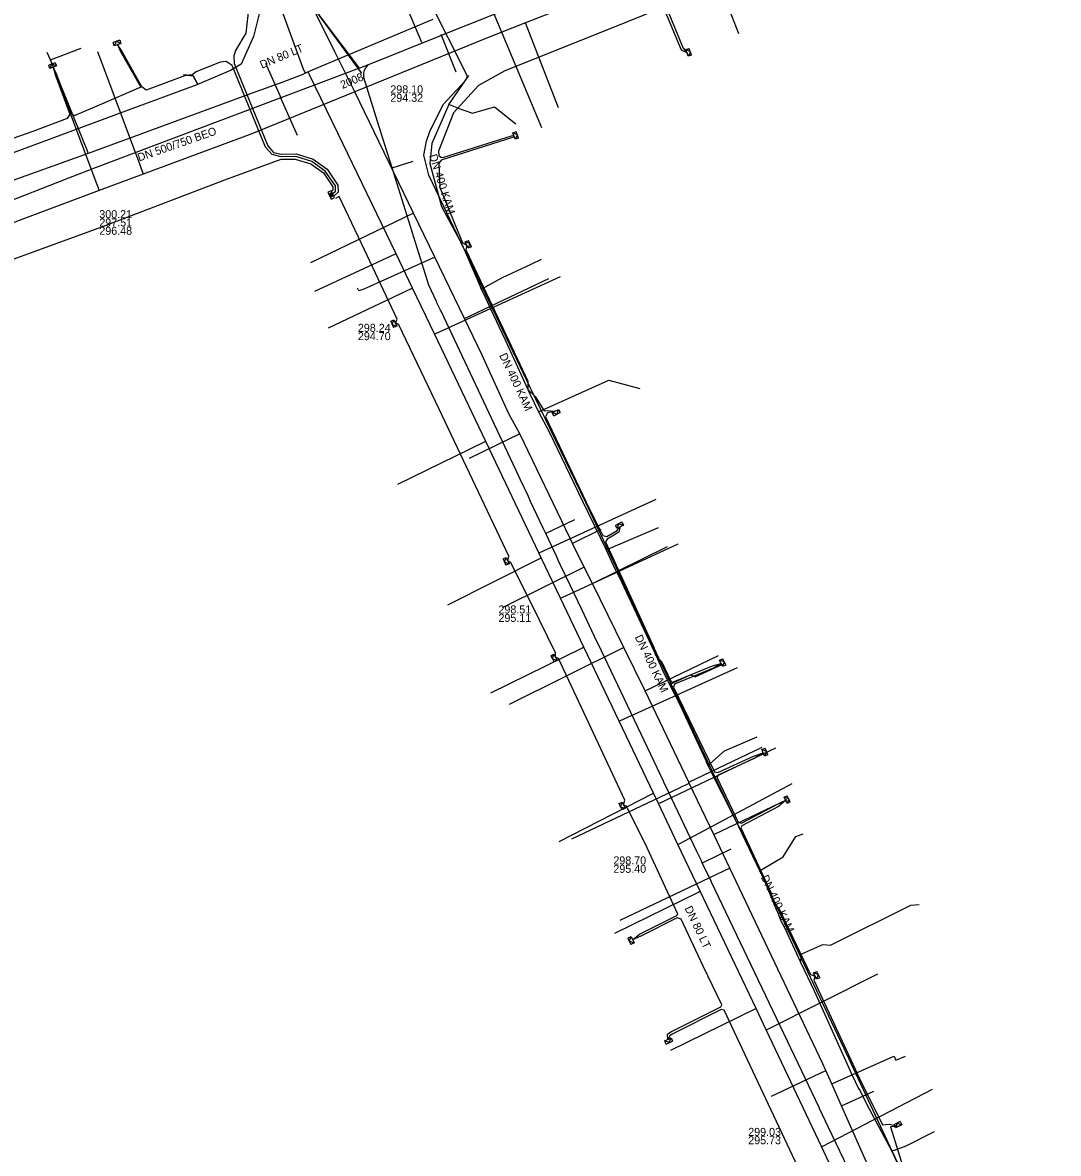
# Model space of a CAD drawing. Extents: x -600391 to -599491, y -1160176 to -1159402.
# Drawn here: x -600264.6 to -600161.2, y -1159777.8 to -1159664.8 of the extents above; entities that cross this region are included whole.
import ezdxf

# ---------------------------------------------------------------- set-up
doc = ezdxf.new("R2010")
doc.units = 0
for name, color, linetype in [('28', 7, 'Continuous'), ('31', 7, 'Continuous'), ('UPC_ok_linie', 7, 'Continuous'), ('Vrstva 1', 7, 'Continuous'), ('Vrstva 12', 7, 'Continuous'), ('Vrstva 13', 7, 'Continuous'), ('Vrstva 15', 7, 'Continuous'), ('Vrstva 16', 7, 'Continuous'), ('Vrstva 42', 7, 'Continuous'), ('Vrstva 43', 7, 'Continuous'), ('Vrstva 55', 7, 'Continuous'), ('Vrstva 9', 7, 'Continuous')]:
    doc.layers.add(name, color=color, linetype=linetype)

# ---------------------------------------------------------------- blocks, each defined once
blk = doc.blocks.new('NN630')
at = {"layer": '31'}
for points in [[(0, -0.7), (-0.7, 0)], [(-0.7, -0.7), (-0.7, 0), (0.7, 0), (0.7, -0.7)], [(-0.7, -0.7), (0.7, -0.7)], [(0, -0.7), (0.7, 0)]]:
    blk.add_lwpolyline(points, dxfattribs=at)
blk = doc.blocks.new('NN620')
at = {"layer": '28'}
for points in [[(0.75, 0), (-0.75, 0)], [(-0.75, 0), (-0.75, -0.75)], [(0.75, -0.75), (0.75, 0)], [(-0.75, -0.75), (0.75, -0.75)], [(0.37, -0.18), (-0.38, -0.18)], [(-0.38, -0.18), (-0.38, -0.56)], [(-0.38, -0.56), (0.37, -0.56)], [(0.32, -0.23), (-0.33, -0.23)], [(-0.33, -0.23), (-0.33, -0.51)], [(-0.33, -0.51), (0.32, -0.51)], [(0.27, -0.27), (-0.28, -0.27)], [(-0.28, -0.27), (-0.28, -0.46)], [(-0.28, -0.46), (0.27, -0.46)], [(0.23, -0.32), (-0.23, -0.32)], [(-0.23, -0.32), (-0.23, -0.42)], [(-0.23, -0.42), (0.23, -0.42)], [(-0.19, -0.37), (0.19, -0.37)], [(0.23, -0.42), (0.23, -0.32)], [(0.27, -0.46), (0.27, -0.27)], [(0.32, -0.51), (0.32, -0.23)], [(0.37, -0.56), (0.37, -0.18)]]:
    blk.add_lwpolyline(points, dxfattribs=at)

msp = doc.modelspace()

# ---------------------------------------------------------------- linework, layer by layer
at = {"layer": 'UPC_ok_linie'}
for p, q in [((-600222.07, -1159672.98), (-600220.06, -1159670.1)), ((-600221.23, -1159673.3), (-600222.07, -1159672.98)), ((-600206.36, -1159717.5), (-600201.11, -1159715.26))]:
    msp.add_line(p, q, dxfattribs=at)
for points in [[(-600222.07, -1159672.98), (-600223.78, -1159676.87), (-600223.98, -1159678.89), (-600222.8, -1159683.16), (-600220.73, -1159687.01), (-600219.02, -1159690.99), (-600218.84, -1159691.43)], [(-600221.23, -1159673.3), (-600219.69, -1159673.85), (-600217.51, -1159673.22), (-600215.38, -1159674.93)], [(-600218.84, -1159691.43), (-600216.7, -1159690.26), (-600213.83, -1159688.93), (-600212.8, -1159688.45)], [(-600218.84, -1159691.43), (-600218.58, -1159691.95), (-600217.89, -1159693.4), (-600216.44, -1159696.5), (-600213.99, -1159701.89), (-600213.1, -1159703.68)], [(-600213.1, -1159703.68), (-600206.08, -1159700.53), (-600202.98, -1159701.37)], [(-600213.1, -1159703.68), (-600212.07, -1159705.64), (-600208.71, -1159712.61), (-600206.36, -1159717.5)], [(-600206.36, -1159717.5), (-600205.52, -1159719.32), (-600205.05, -1159720.19), (-600204.83, -1159720.68), (-600201.34, -1159728.08), (-600200.7, -1159729.59), (-600200.26, -1159730.47), (-600200.04, -1159730.95)], [(-600200.04, -1159730.95), (-600197.93, -1159729.97), (-600197.45, -1159730.17), (-600194.7, -1159728.91)], [(-600200.04, -1159730.95), (-600199.09, -1159732.73), (-600196.38, -1159738.52), (-600196.33, -1159738.72), (-600196.16, -1159739.1)], [(-600196.16, -1159739.1), (-600195.98, -1159738.87), (-600194.54, -1159737.57), (-600191.26, -1159736.17)], [(-600196.16, -1159739.1), (-600195.97, -1159739.51), (-600194.76, -1159741.88), (-600192.01, -1159747.32), (-600190.97, -1159749.54)], [(-600190.97, -1159749.54), (-600188.68, -1159748.16), (-600187.4, -1159746.13), (-600186.66, -1159745.88)], [(-600190.97, -1159749.54), (-600189.42, -1159753.25), (-600189.21, -1159753.77), (-600188.9, -1159754.57)], [(-600186.93, -1159758.68), (-600186.89, -1159758.44), (-600186.8, -1159757.87), (-600184.72, -1159756.94), (-600183.95, -1159757), (-600175.93, -1159752.98), (-600175.08, -1159752.94)], [(-600188.9, -1159754.57), (-600188.54, -1159755.21), (-600186.93, -1159758.68)], [(-600186.93, -1159758.68), (-600185.59, -1159761.56), (-600181.82, -1159769.9), (-600181.14, -1159771.3), (-600180.99, -1159771.54), (-600180.31, -1159772.92), (-600177.86, -1159777.5)], [(-600177.86, -1159777.5), (-600177.54, -1159777.46), (-600176.4, -1159777.03), (-600173.57, -1159775.61)], [(-600177.86, -1159777.5), (-600170.81, -1159792.72), (-600170.15, -1159793.98), (-600169.79, -1159794.82)]]:
    msp.add_lwpolyline(points, dxfattribs=at)
at = {"layer": 'Vrstva 1'}
for points in [[(-600230.8, -1159669.87), (-600230.8, -1159669.82), (-600244.13, -1159651.58)], [(-600224.77, -1159666.77), (-600226.13, -1159663.54)], [(-600221.33, -1159669.76), (-600222.82, -1159665.98)], [(-600238.79, -1159672.43), (-600240.35, -1159668.87)], [(-600237.2, -1159676.09), (-600238.82, -1159672.43)], [(-600227.74, -1159679.3), (-600225.62, -1159678.64)], [(-600209.5, -1159714.48), (-600212.39, -1159715.86)], [(-600193.9, -1159747.41), (-600196.71, -1159748.76)]]:
    msp.add_lwpolyline(points, dxfattribs=at)
at = {"layer": 'Vrstva 13'}
for p, q in [((-600197.8, -1159653.93), (-600193.12, -1159665.9)), ((-600218.25, -1159662.29), (-600212.82, -1159675.29)), ((-600261.87, -1159668.51), (-600258.8, -1159667.34)), ((-600236.4, -1159669.86), (-600236.64, -1159669.98)), ((-600236.4, -1159669.86), (-600236.55, -1159669.55)), ((-600235.99, -1159670.03), (-600236.13, -1159669.73)), ((-600238.64, -1159670.74), (-600238.65, -1159670.72)), ((-600233.15, -1159675.83), (-600233.13, -1159675.82))]:
    msp.add_line(p, q, dxfattribs=at)
for points in [[(-600236.55, -1159669.55), (-600238.62, -1159663.92), (-600239.77, -1159661.76), (-600245.4, -1159651.67), (-600249.45, -1159643.65), (-600250.94, -1159640.72), (-600257.51, -1159628.87), (-600262.81, -1159619.3), (-600263.06, -1159618.85), (-600264.09, -1159617), (-600272.21, -1159603.6), (-600272.38, -1159603.32)], [(-600223.67, -1159664.49), (-600224.22, -1159664.72), (-600236.13, -1159669.73), (-600236.4, -1159669.86)], [(-600258.09, -1159677.89), (-600258.14, -1159677.72), (-600261.87, -1159668.51), (-600262.18, -1159667.79)], [(-600236.64, -1159669.98), (-600238.64, -1159670.74), (-600241.34, -1159671.7)], [(-600161.18, -1159826.62), (-600168.95, -1159810.66), (-600176.39, -1159794.77), (-600178.7, -1159789.98), (-600183.86, -1159779.17), (-600184.83, -1159777.12), (-600190.37, -1159765.45), (-600191.37, -1159763.33), (-600196.96, -1159751.61), (-600199.19, -1159746.92), (-600201.13, -1159742.84), (-600201.62, -1159741.81), (-600205.05, -1159734.61), (-600208.57, -1159727.22), (-600210.91, -1159722.31), (-600212.83, -1159718.29), (-600213.07, -1159717.78), (-600218.37, -1159706.66), (-600223.5, -1159695.91), (-600225.68, -1159691.33), (-600227.32, -1159687.89), (-600233.15, -1159675.83), (-600235.99, -1159670.03)], [(-600241.34, -1159671.7), (-600258.09, -1159677.89), (-600279.4, -1159685.51), (-600279.76, -1159685.64), (-600286.88, -1159688.33), (-600307.79, -1159695.54), (-600308.6, -1159695.85), (-600320.75, -1159700.28), (-600329.04, -1159703.28)], [(-600227.32, -1159687.89), (-600227.44, -1159687.95), (-600235.47, -1159691.67)], [(-600223.5, -1159695.91), (-600223.37, -1159695.85), (-600210.92, -1159690.17)], [(-600225.68, -1159691.33), (-600225.77, -1159691.37), (-600234.12, -1159695.34)], [(-600218.37, -1159706.66), (-600218.47, -1159706.7), (-600227.19, -1159710.95)], [(-600213.07, -1159717.78), (-600212.98, -1159717.74), (-600201.35, -1159712.41)], [(-600210.91, -1159722.31), (-600210.73, -1159722.24), (-600199.16, -1159716.89)], [(-600212.83, -1159718.29), (-600212.93, -1159718.34), (-600222.19, -1159723.02)], [(-600208.57, -1159727.22), (-600208.76, -1159727.32), (-600217.89, -1159731.81)], [(-600205.05, -1159734.61), (-600204.93, -1159734.55), (-600193.23, -1159729.25)], [(-600201.13, -1159742.84), (-600201.08, -1159742.82), (-600189.4, -1159737.28)], [(-600199.19, -1159746.92), (-600198.98, -1159746.83), (-600187.76, -1159740.85)], [(-600201.62, -1159741.81), (-600201.72, -1159741.86), (-600211.07, -1159746.68)], [(-600196.96, -1159751.61), (-600197.11, -1159751.68), (-600205.52, -1159755.83)], [(-600190.37, -1159765.45), (-600190.35, -1159765.44), (-600179.2, -1159759.85)], [(-600191.37, -1159763.33), (-600191.42, -1159763.35), (-600199.91, -1159767.52)], [(-600184.83, -1159777.12), (-600184.78, -1159777.1), (-600173.76, -1159771.38)]]:
    msp.add_lwpolyline(points, dxfattribs=at)
at = {"layer": 'Vrstva 16'}
for points in [[(-600256.94, -1159591.71), (-600258.09, -1159592.42), (-600270.56, -1159600.02), (-600267.59, -1159605.02), (-600264.25, -1159610.67), (-600261.26, -1159616.28), (-600261.19, -1159616.42), (-600258.03, -1159622.25), (-600255.77, -1159626.44), (-600244.99, -1159645.87), (-600239.51, -1159655.75), (-600239.15, -1159656.4), (-600233.5, -1159667.64)], [(-600192.98, -1159656.42), (-600214.42, -1159664.83), (-600218.2, -1159666.31), (-600231.45, -1159671.73), (-600241.75, -1159675.9), (-600252.59, -1159679.95), (-600257, -1159681.59), (-600273.19, -1159687.64), (-600281.2, -1159690.52), (-600282.61, -1159691.03), (-600286.19, -1159692.31), (-600306.49, -1159699.61), (-600317.46, -1159703.55), (-600317.98, -1159703.74), (-600319.12, -1159704.16), (-600321.16, -1159704.92), (-600324.82, -1159706.29), (-600332.07, -1159708.92)], [(-600211.1, -1159673.3), (-600214.02, -1159665.86), (-600214.42, -1159664.83)], [(-600257.17, -1159667.69), (-600252.98, -1159678.92), (-600252.59, -1159679.95)], [(-600231.45, -1159671.73), (-600233.5, -1159667.64)], [(-600261.58, -1159669.33), (-600257.52, -1159680.19), (-600257, -1159681.59)], [(-600179.95, -1159779.58), (-600182.83, -1159773.03), (-600183.81, -1159770.84), (-600184.41, -1159769.5), (-600184.7, -1159768.84), (-600187.26, -1159763.46), (-600194, -1159749.3), (-600195.6, -1159745.92), (-600198.05, -1159740.79), (-600198.1, -1159740.69), (-600202.44, -1159731.56), (-600204.57, -1159727.26), (-600207.73, -1159720.86), (-600208.54, -1159719.23), (-600209.72, -1159716.84), (-600209.96, -1159716.35), (-600214.97, -1159705.89), (-600216.09, -1159703.89), (-600218.78, -1159697.96), (-600220.51, -1159694.38), (-600223.46, -1159688.25), (-600225.59, -1159683.84), (-600231.45, -1159671.73)], [(-600225.59, -1159683.84), (-600235.89, -1159688.82)], [(-600223.46, -1159688.25), (-600230.57, -1159691.42)], [(-600220.51, -1159694.38), (-600212.08, -1159690.38)], [(-600230.57, -1159691.42), (-600231.07, -1159691.61), (-600231.2, -1159691.35)], [(-600214.97, -1159705.89), (-600220.03, -1159708.37)], [(-600206.89, -1159715.45), (-600209.72, -1159716.84)], [(-600207.73, -1159720.86), (-600200.23, -1159717.15)], [(-600208.54, -1159719.23), (-600216.68, -1159723.25), (-600216.69, -1159723.26)], [(-600204.57, -1159727.26), (-600216.03, -1159732.94)], [(-600202.44, -1159731.56), (-600195.12, -1159728.06)], [(-600198.1, -1159740.69), (-600190.76, -1159737.19)], [(-600209.77, -1159746.37), (-600199.04, -1159741.26), (-600198.05, -1159740.79)], [(-600195.6, -1159745.92), (-600188.27, -1159742.43)], [(-600194, -1159749.3), (-600205, -1159754.54)], [(-600183.81, -1159770.84), (-600177.67, -1159768.1)], [(-600177.67, -1159768.1), (-600177.59, -1159768.07), (-600177.41, -1159768.47), (-600176.45, -1159768.07)], [(-600189.84, -1159772.08), (-600184.41, -1159769.5)], [(-600182.83, -1159773.03), (-600179.6, -1159771.59)]]:
    msp.add_lwpolyline(points, dxfattribs=at)
at = {"layer": 'Vrstva 42'}
for points in [[(-600242.04, -1159663.18), (-600242.35, -1159665.85), (-600243.38, -1159667.57), (-600243.55, -1159668.16), (-600243.51, -1159668.9), (-600240.15, -1159677.1), (-600239.59, -1159677.77), (-600238.77, -1159677.96), (-600237.33, -1159677.92), (-600235.63, -1159678.46), (-600234.23, -1159679.46), (-600233.15, -1159681.04), (-600233.13, -1159681.74), (-600233.52, -1159682.11)], [(-600200.86, -1159663.34), (-600206.23, -1159665.51), (-600216.47, -1159669.62), (-600219.1, -1159671.09), (-600221.6, -1159673.82), (-600223.09, -1159677.65), (-600223.08, -1159678.09), (-600222.88, -1159678.24), (-600222.66, -1159678.27), (-600215.7, -1159676.07), (-600215.55, -1159676.13), (-600215.61, -1159676.26), (-600222.83, -1159678.56), (-600223.05, -1159678.88), (-600222.95, -1159681.28), (-600220.7, -1159686.81), (-600220.28, -1159687.03), (-600220.37, -1159687.5), (-600216.86, -1159694.91), (-600214.19, -1159700.64), (-600214.18, -1159701.47), (-600213.44, -1159702.16), (-600212.54, -1159703.61), (-600212.38, -1159703.55), (-600211.43, -1159703.63), (-600212.22, -1159703.79), (-600212.4, -1159704.18), (-600208.34, -1159712.71), (-600206.69, -1159716.05), (-600206.3, -1159716.15), (-600205.25, -1159715.55), (-600204.94, -1159715.19), (-600205.07, -1159715.73), (-600206.26, -1159716.42), (-600206.42, -1159716.69), (-600201.57, -1159727.32), (-600201.45, -1159727.99), (-600200.83, -1159728.65), (-600199.86, -1159730.68), (-600199.74, -1159730.72), (-600195.73, -1159729.06), (-600194.87, -1159728.83)], [(-600200.27, -1159663.48), (-600198.66, -1159667.35), (-600198.27, -1159667.83), (-600198.84, -1159667.55), (-600200.47, -1159663.64)], [(-600233.64, -1159681.87), (-600233.38, -1159681.64), (-600233.4, -1159681.12), (-600234.41, -1159679.63), (-600235.74, -1159678.68), (-600237.36, -1159678.18), (-600238.8, -1159678.21), (-600239.73, -1159677.99), (-600240.37, -1159677.23), (-600243.71, -1159669.07), (-600244.3, -1159668.69), (-600244.92, -1159668.76), (-600247.3, -1159669.71), (-600247.72, -1159670.01), (-600248.37, -1159670.08), (-600252.31, -1159671.56), (-600252.73, -1159671.2), (-600254.77, -1159667.58), (-600255.16, -1159667), (-600254.89, -1159667.61), (-600252.84, -1159671.25), (-600257.01, -1159673.04), (-600259.5, -1159674.13), (-600259.8, -1159673.88), (-600261.23, -1159670.03), (-600261.59, -1159669.25), (-600261.36, -1159670.09), (-600259.92, -1159673.95), (-600260.19, -1159674.38), (-600263.62, -1159675.69), (-600272.12, -1159678.65)], [(-600322.85, -1159710.15), (-600322.7, -1159709.9), (-600322.77, -1159709.65), (-600313.2, -1159706.13), (-600304.18, -1159702.71), (-600294.33, -1159699.1), (-600292.93, -1159698.41), (-600281.8, -1159694.34), (-600281.7, -1159694.57), (-600281.08, -1159695.3), (-600281.43, -1159694.54), (-600281.29, -1159694.16), (-600268.36, -1159689.44), (-600256.73, -1159685.19), (-600244.45, -1159680.52), (-600238.83, -1159678.46), (-600237.4, -1159678.43), (-600235.85, -1159678.91), (-600234.59, -1159679.81), (-600233.65, -1159681.2), (-600233.64, -1159681.53), (-600233.75, -1159681.63)], [(-600185.62, -1159782.53), (-600190.14, -1159772.91), (-600194.55, -1159763.48), (-600194.85, -1159763.42), (-600199.77, -1159765.87), (-600199.99, -1159766.04), (-600200.19, -1159766.41), (-600200.21, -1159765.9), (-600199.9, -1159765.66), (-600194.89, -1159763.16), (-600194.79, -1159762.95), (-600196.66, -1159759.09), (-600198.85, -1159754.38), (-600199.27, -1159754.27), (-600202.88, -1159756.09), (-600203.71, -1159756.45), (-600203.03, -1159755.88), (-600199.3, -1159754.01), (-600199.19, -1159753.88), (-600202.27, -1159747.25), (-600204.33, -1159743.09), (-600204.61, -1159743), (-600204.48, -1159742.49), (-600208.82, -1159733.25), (-600211.12, -1159728.33), (-600211.41, -1159728.2), (-600211.41, -1159727.77), (-600213, -1159724.51), (-600215.86, -1159718.75), (-600216.19, -1159718.57), (-600216.06, -1159718.13), (-600223.03, -1159703.43), (-600227.05, -1159694.99), (-600227.41, -1159694.81), (-600227.24, -1159694.43), (-600230.49, -1159687.51), (-600233.03, -1159682.17), (-600233.39, -1159682.38)], [(-600194.87, -1159728.83), (-600195.56, -1159729.26), (-600199.54, -1159730.91), (-600199.62, -1159731.21), (-600197.58, -1159735.42), (-600195.53, -1159739.68), (-600195.19, -1159739.74), (-600191.62, -1159738.09), (-600190.67, -1159737.77), (-600191.51, -1159738.3), (-600195.16, -1159740), (-600195.29, -1159740.2), (-600193.16, -1159744.69), (-600192.83, -1159744.8), (-600189.24, -1159742.9), (-600188.43, -1159742.52), (-600189.14, -1159743.12), (-600192.81, -1159745.07), (-600192.89, -1159745.25), (-600189.82, -1159751.86), (-600189.76, -1159752.57), (-600189.11, -1159753.28), (-600185.94, -1159759.92), (-600185.48, -1159760.08), (-600185.6, -1159760.49), (-600181.05, -1159770.33), (-600178.75, -1159774.93), (-600178.07, -1159774.88), (-600177.14, -1159775.09), (-600177.95, -1159775.13), (-600176.42, -1159780.07)]]:
    msp.add_lwpolyline(points, dxfattribs=at)
at = {"layer": 'Vrstva 55'}
for points in [[(-600240.74, -1159662.87), (-600241.57, -1159666.19), (-600242.8, -1159668.94), (-600243.89, -1159669.57), (-600247.02, -1159670.93), (-600247.13, -1159670.98), (-600247.62, -1159670.12), (-600248.56, -1159670.03), (-600247.62, -1159670.12), (-600247.13, -1159670.98), (-600254.36, -1159673.64), (-600267.94, -1159678.68)], [(-600176.01, -1159781.35), (-600182.61, -1159767.26), (-600189.25, -1159753.26), (-600195.55, -1159740), (-600200.83, -1159728.87), (-600208.39, -1159712.75), (-600213.9, -1159701.34), (-600219.07, -1159690.51), (-600224.07, -1159680.03), (-600224.56, -1159678.05), (-600224.29, -1159676.66), (-600223.97, -1159675.67), (-600222.62, -1159672.99), (-600220.36, -1159670.56), (-600220.21, -1159670.16), (-600224.03, -1159662.54)]]:
    msp.add_lwpolyline(points, dxfattribs=at)
at = {"layer": 'Vrstva 9'}
for p, q in [((-600231.04, -1159669.34), (-600229.83, -1159668.88)), ((-600292.91, -1159693.12), (-600260.02, -1159680.32))]:
    msp.add_line(p, q, dxfattribs=at)
for points in [[(-600244.25, -1159651.59), (-600239.3, -1159658.35), (-600231.04, -1159669.34)], [(-600229.83, -1159668.88), (-600223.53, -1159666.35), (-600223.35, -1159666.28), (-600223.33, -1159666.27), (-600222.98, -1159666.13), (-600214.85, -1159662.89), (-600196.55, -1159655.61), (-600196.48, -1159655.58), (-600192.88, -1159654.15)], [(-600224.08, -1159691.03), (-600227.74, -1159679.3), (-600228.85, -1159675.74), (-600230.55, -1159670.29), (-600230.57, -1159670.06), (-600230.56, -1159669.83), (-600230.48, -1159669.54), (-600230.37, -1159669.31), (-600230.24, -1159669.15), (-600230.08, -1159668.98), (-600229.83, -1159668.88)], [(-600260.02, -1159680.32), (-600257.26, -1159679.25), (-600251.26, -1159676.98), (-600238.81, -1159672.28), (-600231.05, -1159669.34), (-600231.04, -1159669.34)], [(-600209.95, -1159721.02), (-600210.93, -1159718.95), (-600211.13, -1159718.51), (-600211.28, -1159718.2), (-600211.59, -1159717.54), (-600212.39, -1159715.84), (-600212.64, -1159715.31), (-600213.9, -1159712.64), (-600214.12, -1159712.17), (-600214.94, -1159710.43), (-600215.11, -1159710.07), (-600222.84, -1159693.65), (-600222.9, -1159693.53), (-600223.25, -1159692.79), (-600223.3, -1159692.68), (-600224.08, -1159691.03)], [(-600197.33, -1159747.55), (-600198.55, -1159744.98), (-600200.1, -1159741.72), (-600200.59, -1159740.7), (-600200.64, -1159740.6), (-600203.2, -1159735.21), (-600204.23, -1159733.05), (-600206.82, -1159727.59), (-600206.9, -1159727.42), (-600207.28, -1159726.63), (-600208.76, -1159723.52), (-600209.95, -1159721.02)], [(-600184.13, -1159775.21), (-600185.04, -1159773.3), (-600185.05, -1159773.28), (-600185.78, -1159771.75), (-600185.81, -1159771.69), (-600186.81, -1159769.59), (-600186.82, -1159769.58), (-600195.83, -1159750.69), (-600195.84, -1159750.66), (-600196.75, -1159748.76), (-600196.84, -1159748.57), (-600197.33, -1159747.55)], [(-600171.83, -1159801.11), (-600173.77, -1159797.02), (-600173.81, -1159796.93), (-600175.31, -1159793.77), (-600175.37, -1159793.65), (-600182.11, -1159779.46), (-600182.15, -1159779.38), (-600182.51, -1159778.61), (-600182.6, -1159778.42), (-600184.13, -1159775.21)]]:
    msp.add_lwpolyline(points, dxfattribs=at)

# ---------------------------------------------------------------- block references
at = {"layer": 'Vrstva 43'}
for name, p, xscale, yscale, rotation in [('NN630', (-600255.16, -1159667), 0.5000000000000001, 0.5, -161.00000000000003), ('NN630', (-600198.27, -1159667.83), 0.5, 0.5, 110), ('NN630', (-600261.59, -1159669.25), 0.5, 0.5, -160.00000000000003), ('NN630', (-600215.55, -1159676.13), 0.5, 0.5, 111), ('NN620', (-600233.64, -1159681.93), 0.5000000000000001, 0.4999999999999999, -64), ('NN630', (-600220.28, -1159687.03), 0.5000000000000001, 0.5, 115), ('NN630', (-600227.41, -1159694.81), 0.5, 0.5, -66.00000000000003), ('NN630', (-600211.43, -1159703.63), 0.5, 0.5, 29.00000000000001), ('NN630', (-600204.94, -1159715.19), 0.5000000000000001, 0.4999999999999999, -151), ('NN630', (-600216.19, -1159718.57), 0.5, 0.5, -66.00000000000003), ('NN630', (-600211.41, -1159728.2), 0.5, 0.5, -61.000000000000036), ('NN630', (-600194.87, -1159728.83), 0.5000000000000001, 0.5, 115), ('NN630', (-600190.66, -1159737.77), 0.49999999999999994, 0.5000000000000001, 113), ('NN630', (-600188.43, -1159742.52), 0.5000000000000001, 0.5000000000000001, 116.00000000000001), ('NN630', (-600204.61, -1159743), 0.5, 0.5, -63.000000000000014), ('NN630', (-600203.71, -1159756.45), 0.5000000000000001, 0.4999999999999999, -64), ('NN630', (-600185.48, -1159760.08), 0.5000000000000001, 0.5000000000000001, 116.00000000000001), ('NN630', (-600200.19, -1159766.41), 0.49999999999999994, 0.5000000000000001, 25), ('NN630', (-600177.14, -1159775.09), 0.5, 0.5, -153)]:
    msp.add_blockref(name, p, dxfattribs=dict(at, xscale=xscale, yscale=yscale, rotation=rotation))

# ---------------------------------------------------------------- texts
at = {"layer": 'Vrstva 12'}
for s, p in [('298.10', (-600227.91, -1159671.87)), ('294.32', (-600227.91, -1159672.71)), ('300.21', (-600256.98, -1159684.34)), ('297.51', (-600256.98, -1159685.17)), ('296.48', (-600256.98, -1159686)), ('298.24', (-600231.15, -1159695.7)), ('294.70', (-600231.15, -1159696.53)), ('298.51', (-600217.11, -1159723.84)), ('295.11', (-600217.11, -1159724.68)), ('298.70', (-600205.63, -1159748.92)), ('295.40', (-600205.63, -1159749.76)), ('299.03', (-600192.16, -1159776.05)), ('295.73', (-600192.16, -1159776.88))]:
    msp.add_text(s, height=0.8, dxfattribs=at).set_placement(p)
for s, rotation, p in [('DN 500/750 BEO', 19.2514, (-600253, -1159678.68)), ('DN 400 KAM', 287.3383, (-600224.04, -1159678.08)), ('DN 400 KAM', 295.1879, (-600217.05, -1159698.05)), ('DN 400 KAM', 295.4743, (-600203.51, -1159726.2)), ('DN 400 KAM', 295.5316, (-600190.92, -1159750.2))]:
    msp.add_text(s, height=0.8, rotation=rotation, dxfattribs=at).set_placement(p)
at = {"layer": 'Vrstva 15'}
for s, rotation, p in [('DN 80 LT', 22.8037, (-600240.74, -1159669.42)), ('2008', 22.8037, (-600232.7, -1159671.44)), ('DN 80 LT', 295.4743, (-600198.54, -1159753.3))]:
    msp.add_text(s, height=0.8, rotation=rotation, dxfattribs=at).set_placement(p)

doc.saveas('drawing.dxf')
